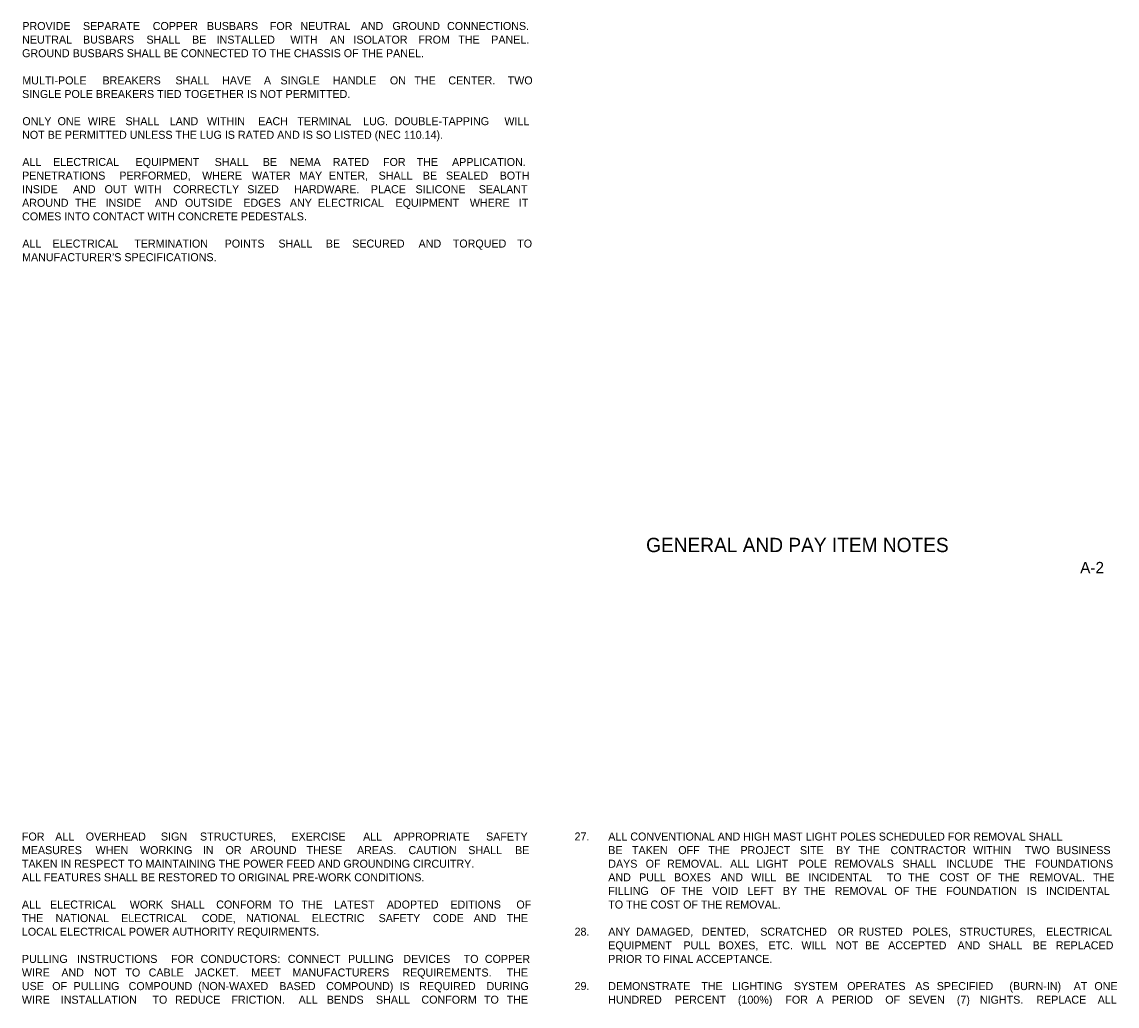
# Model space of a CAD drawing. Extents: x -55 to 2471539, y -90 to 3608906.
# Drawn here: x 568 to 1526, y 780 to 1641 of the extents above; entities that cross this region are included whole.
import ezdxf

# ---------------------------------------------------------------- set-up
doc = ezdxf.new("R2010")
doc.units = 0
for name, color, linetype in [('SheetLines_dp', 7, 'Continuous'), ('TextMisc', 7, 'Continuous'), ('XSCell', 7, 'Continuous')]:
    doc.layers.add(name, color=color, linetype=linetype)

msp = doc.modelspace()

# ---------------------------------------------------------------- texts
at = {"layer": 'SheetLines_dp'}
msp.add_text('A-2', height=10, dxfattribs=at).set_placement((1493.84, 1158.67))
at = {"layer": 'TextMisc'}
msp.add_text('GENERAL AND PAY ITEM NOTES ', height=12.5, dxfattribs=at).set_placement((1114.08, 1177.24))
at = {"layer": 'XSCell'}
for s, p in [('PROVIDE ', (568.41, 1634.16)), ('SEPARATE ', (621.45, 1634.16)), ('COPPER ', (682.49, 1634.16)), ('BUSBARS ', (729.91, 1634.16)), ('FOR ', (784.97, 1634.16)), ('NEUTRAL ', (811.68, 1634.16)), ('AND ', (864.42, 1634.16)), ('GROUND ', (892.2, 1634.16)), ('CONNECTIONS. ', (939.94, 1634.16)), ('NEUTRAL ', (568.21, 1622.26)), ('BUSBARS ', (621.45, 1622.26)), ('SHALL ', (677.01, 1622.26)), ('BE ', (716.92, 1622.26)), ('INSTALLED ', (738.38, 1622.26)), ('WITH ', (802.88, 1622.26)), ('AN ', (837.46, 1622.26)), ('ISOLATOR ', (858.06, 1622.26)), ('FROM ', (914.87, 1622.26)), ('THE ', (949.8, 1622.26)), ('PANEL. ', (978.63, 1622.26)), ('GROUND BUSBARS SHALL BE CONNECTED TO THE CHASSIS OF THE PANEL.', (568.21, 1610.36)), ('MULTI-POLE ', (568.41, 1586.56)), ('BREAKERS ', (638.51, 1586.56)), ('SHALL ', (702.38, 1586.56)), ('HAVE ', (743.16, 1586.56)), ('A ', (779.74, 1586.56)), ('SINGLE ', (794.27, 1586.56)), ('HANDLE ', (840.04, 1586.56)), ('ON ', (889.95, 1586.56)), ('THE ', (911.39, 1586.56)), ('CENTER. ', (941.09, 1586.56)), ('TWO ', (992.99, 1586.56)), ('SINGLE POLE BREAKERS TIED TOGETHER IS NOT PERMITTED.', (568.21, 1574.66)), ('ONLY ', (568.41, 1550.86)), ('ONE ', (599.23, 1550.86)), ('WIRE ', (625.7, 1550.86)), ('SHALL ', (658.63, 1550.86)), ('LAND ', (697.32, 1550.86)), ('WITHIN ', (729.93, 1550.86)), ('EACH ', (774.76, 1550.86)), ('TERMINAL ', (808.97, 1550.86)), ('LUG. ', (866.54, 1550.86)), ('DOUBLE-TAPPING ', (893.99, 1550.86)), ('WILL ', (990.11, 1550.86)), ('NOT BE PERMITTED UNLESS THE LUG IS RATED AND IS SO LISTED (NEC 110.14).', (568.21, 1538.96)), ('ALL ', (568.41, 1515.16)), ('ELECTRICAL ', (595.35, 1515.16)), ('EQUIPMENT ', (667.45, 1515.16)), ('SHALL ', (736.66, 1515.16)), ('BE ', (778.74, 1515.16)), ('NEMA ', (802.38, 1515.16)), ('RATED ', (840.02, 1515.16)), ('FOR ', (883.93, 1515.16)), ('THE ', (913.32, 1515.16)), ('APPLICATION. ', (944.32, 1515.16)), ('PENETRATIONS ', (568.21, 1503.26)), ('PERFORMED, ', (653.26, 1503.26)), ('WHERE ', (725.72, 1503.26)), ('WATER ', (769.3, 1503.26)), ('MAY ', (810.47, 1503.26)), ('ENTER, ', (836.56, 1503.26)), ('SHALL ', (880.09, 1503.26)), ('BE ', (918.76, 1503.26)), ('SEALED ', (938.99, 1503.26)), ('BOTH ', (986, 1503.26)), ('INSIDE ', (568.21, 1491.36)), ('AND ', (612.71, 1491.36)), ('OUT ', (640.35, 1491.36)), ('WITH ', (666.41, 1491.36)), ('CORRECTLY ', (700.34, 1491.36)), ('SIZED ', (765.18, 1491.36)), ('HARDWARE. ', (806.08, 1491.36)), ('PLACE ', (873.27, 1491.36)), ('SILICONE ', (912.4, 1491.36)), ('SEALANT ', (967.69, 1491.36)), ('AROUND ', (568.21, 1479.46)), ('THE ', (614.44, 1479.46)), ('INSIDE ', (641.25, 1479.46)), ('AND ', (684.38, 1479.46)), ('OUTSIDE ', (710.65, 1479.46)), ('EDGES ', (761.76, 1479.46)), ('ANY ', (802.44, 1479.46)), ('ELECTRICAL ', (826.96, 1479.46)), ('EQUIPMENT ', (894.87, 1479.46)), ('WHERE ', (959.89, 1479.46)), ('IT ', (1002.69, 1479.46)), ('COMES INTO CONTACT WITH CONCRETE PEDESTALS. ', (568.21, 1467.56)), ('ALL ', (568.41, 1443.76)), ('ELECTRICAL ', (594.79, 1443.76)), ('TERMINATION ', (666.33, 1443.76)), ('POINTS ', (745.4, 1443.76)), ('SHALL ', (792.42, 1443.76)), ('BE ', (833.95, 1443.76)), ('SECURED ', (857.02, 1443.76)), ('AND ', (915.06, 1443.76)), ('TORQUED ', (944.97, 1443.76)), ('TO ', (1001.35, 1443.76)), ('MANUFACTURER’S SPECIFICATIONS.', (568.21, 1431.86)), ('FOR ', (568.01, 924.84)), ('ALL ', (597.18, 924.84)), ('OVERHEAD ', (623.9, 924.84)), ('SIGN ', (689.63, 924.84)), ('STRUCTURES, ', (723.79, 924.84)), ('EXERCISE ', (803.84, 924.84)), ('ALL ', (866.52, 924.84)), ('APPROPRIATE ', (893.24, 924.84)), ('SAFETY ', (974.04, 924.84)), ('27.', (1051.5, 924.88)), ('ALL CONVENTIONAL AND HIGH MAST LIGHT POLES SCHEDULED FOR REMOVAL SHALL ', (1080.99, 924.84)), ('MEASURES ', (568.01, 912.94)), ('WHEN ', (632.51, 912.94)), ('WORKING ', (671.35, 912.94)), ('IN ', (726.33, 912.94)), ('OR ', (746.14, 912.94)), ('AROUND ', (767.73, 912.94)), ('THESE ', (817.07, 912.94)), ('AREAS. ', (861.21, 912.94)), ('CAUTION ', (906.23, 912.94)), ('SHALL ', (958.48, 912.94)), ('BE ', (999.48, 912.94)), ('BE ', (1080.99, 912.94)), ('TAKEN ', (1101.71, 912.94)), ('OFF ', (1142.24, 912.94)), ('THE ', (1168.55, 912.94)), ('PROJECT ', (1196.64, 912.94)), ('SITE ', (1248.68, 912.94)), ('BY ', (1280.31, 912.94)), ('THE ', (1299.83, 912.94)), ('CONTRACTOR ', (1327.91, 912.94)), ('WITHIN ', (1400.14, 912.94)), ('TWO ', (1445.44, 912.94)), ('BUSINESS ', (1473.05, 912.94)), ('TAKEN IN RESPECT TO MAINTAINING THE POWER FEED AND GROUNDING CIRCUITRY. ', (568.01, 901.04)), ('DAYS ', (1080.99, 901.04)), ('OF ', (1113.71, 901.04)), ('REMOVAL. ', (1132.4, 901.04)), ('ALL ', (1187.65, 901.04)), ('LIGHT ', (1210.77, 901.04)), ('POLE ', (1247.3, 901.04)), ('REMOVALS ', (1278.82, 901.04)), ('SHALL ', (1338.4, 901.04)), ('INCLUDE ', (1376.66, 901.04)), ('THE ', (1427.37, 901.04)), ('FOUNDATIONS ', (1454.55, 901.04)), ('ALL FEATURES SHALL BE RESTORED TO ORIGINAL PRE-WORK CONDITIONS.', (568.01, 889.14)), ('AND ', (1080.99, 889.14)), ('PULL ', (1107.94, 889.14)), ('BOXES ', (1138.52, 889.14)), ('AND ', (1179.11, 889.14)), ('WILL ', (1206.05, 889.14)), ('BE ', (1235.94, 889.14)), ('INCIDENTAL ', (1256.06, 889.14)), ('TO ', (1324.63, 889.14)), ('THE ', (1343.28, 889.14)), ('COST ', (1370.76, 889.14)), ('OF ', (1403.06, 889.14)), ('THE ', (1422.05, 889.14)), ('REMOVAL. ', (1449.54, 889.14)), ('THE ', (1505.1, 889.14)), ('FILLING ', (1080.99, 877.24)), ('OF ', (1126.56, 877.24)), ('THE ', (1144.99, 877.24)), ('VOID ', (1171.92, 877.24)), ('LEFT ', (1202.68, 877.24)), ('BY ', (1233.8, 877.24)), ('THE ', (1252.15, 877.24)), ('REMOVAL ', (1279.07, 877.24)), ('OF ', (1331.32, 877.24)), ('THE ', (1349.75, 877.24)), ('FOUNDATION ', (1376.68, 877.24)), ('IS ', (1447.07, 877.24)), ('INCIDENTAL ', (1464.02, 877.24)), ('ALL ', (568.01, 865.34)), ('ELECTRICAL ', (592.62, 865.34)), ('WORK ', (662.4, 865.34)), ('SHALL ', (698.26, 865.34)), ('CONFORM ', (738.02, 865.34)), ('TO ', (792.68, 865.34)), ('THE ', (812.52, 865.34)), ('LATEST ', (841.2, 865.34)), ('ADOPTED ', (887.23, 865.34)), ('EDITIONS ', (942.86, 865.34)), ('OF ', (1000.61, 865.34)), ('TO THE COST OF THE REMOVAL.', (1080.99, 865.34)), ('THE ', (568.01, 853.44)), ('NATIONAL ', (597.45, 853.44)), ('ELECTRICAL ', (654.85, 853.44)), ('CODE, ', (725.4, 853.44)), ('NATIONAL ', (764.08, 853.44)), ('ELECTRIC ', (821.48, 853.44)), ('SAFETY ', (880.07, 853.44)), ('CODE ', (927.59, 853.44)), ('AND ', (963.21, 853.44)), ('THE ', (992.12, 853.44)), ('LOCAL ELECTRICAL POWER AUTHORITY REQUIRMENTS.', (568.01, 841.54)), ('28.', (1051.5, 841.58)), ('ANY ', (1080.99, 841.54)), ('DAMAGED, ', (1105.33, 841.54)), ('DENTED, ', (1162.91, 841.54)), ('SCRATCHED ', (1213.98, 841.54)), ('OR ', (1281.79, 841.54)), ('RUSTED ', (1300.09, 841.54)), ('POLES, ', (1347, 841.54)), ('STRUCTURES, ', (1388.11, 841.54)), ('ELECTRICAL ', (1463.99, 841.54)), ('EQUIPMENT ', (1080.99, 829.64)), ('PULL ', (1146.77, 829.64)), ('BOXES, ', (1177.43, 829.64)), ('ETC. ', (1221.17, 829.64)), ('WILL ', (1249.99, 829.64)), ('NOT ', (1279.96, 829.64)), ('BE ', (1305.64, 829.64)), ('ACCEPTED ', (1325.84, 829.64)), ('AND ', (1386.57, 829.64)), ('SHALL ', (1413.6, 829.64)), ('BE ', (1452.25, 829.64)), ('REPLACED ', (1472.45, 829.64)), ('PULLING ', (568.01, 817.74)), ('INSTRUCTIONS ', (616.36, 817.74)), ('FOR ', (698.53, 817.74)), ('CONDUCTORS: ', (724.3, 817.74)), ('CONNECT ', (800.66, 817.74)), ('PULLING ', (853.35, 817.74)), ('DEVICES ', (901.7, 817.74)), ('TO ', (954.47, 817.74)), ('COPPER ', (973.02, 817.74)), ('PRIOR TO FINAL ACCEPTANCE.', (1080.99, 817.74)), ('WIRE ', (568.01, 805.84)), ('AND ', (602.54, 805.84)), ('NOT ', (631.21, 805.84)), ('TO ', (658.53, 805.84)), ('CABLE ', (678.91, 805.84)), ('JACKET. ', (719.28, 805.84)), ('MEET ', (768.67, 805.84)), ('MANUFACTURERS ', (804.68, 805.84)), ('REQUIREMENTS. ', (900.84, 805.84)), ('THE ', (992.12, 805.84)), ('USE ', (568.01, 793.94)), ('OF ', (594.54, 793.94)), ('PULLING ', (613.24, 793.94)), ('COMPOUND ', (661.39, 793.94)), ('(NON-WAXED ', (722.22, 793.94)), ('BASED ', (793.21, 793.94)), ('COMPOUND) ', (834.21, 793.94)), ('IS ', (898.4, 793.94)), ('REQUIRED ', (915.62, 793.94)), ('DURING ', (974.54, 793.94)), ('29.', (1051.5, 793.98)), ('DEMONSTRATE ', (1080.99, 793.94)), ('THE ', (1162.41, 793.94)), ('LIGHTING ', (1189.29, 793.94)), ('SYSTEM ', (1243.4, 793.94)), ('OPERATES ', (1290.02, 793.94)), ('AS ', (1349.57, 793.94)), ('SPECIFIED ', (1368.37, 793.94)), ('(BURN-IN) ', (1431.91, 793.94)), ('AT ', (1488.15, 793.94)), ('ONE ', (1506.24, 793.94)), ('WIRE ', (568.01, 782.04)), ('INSTALLATION ', (602.03, 782.04)), ('TO ', (682.22, 782.04)), ('REDUCE ', (702.09, 782.04)), ('FRICTION. ', (751.31, 782.04)), ('ALL ', (810.1, 782.04)), ('BENDS ', (834.73, 782.04)), ('SHALL ', (877.78, 782.04)), ('CONFORM ', (917.56, 782.04)), ('TO ', (972.25, 782.04)), ('THE ', (992.12, 782.04)), ('HUNDRED ', (1080.99, 782.04)), ('PERCENT ', (1139.28, 782.04)), ('(100%) ', (1194.36, 782.04)), ('FOR ', (1235.9, 782.04)), ('A ', (1263.05, 782.04)), ('PERIOD ', (1276.66, 782.04)), ('OF ', (1323.31, 782.04)), ('SEVEN ', (1343.59, 782.04)), ('(7) ', (1385.9, 782.04)), ('NIGHTS. ', (1406.09, 782.04)), ('REPLACE ', (1455.44, 782.04)), ('ALL ', (1509.17, 782.04))]:
    msp.add_text(s, height=7, dxfattribs=at).set_placement(p)

doc.saveas('drawing.dxf')
